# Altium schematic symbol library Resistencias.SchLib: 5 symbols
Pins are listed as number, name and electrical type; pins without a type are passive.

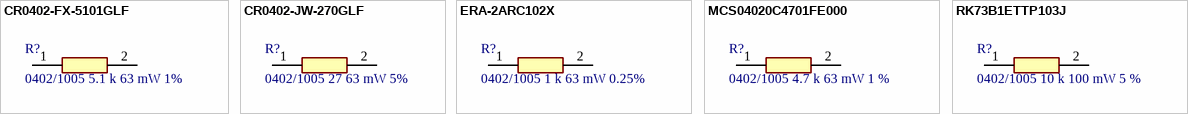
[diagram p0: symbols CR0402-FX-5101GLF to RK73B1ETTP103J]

## CR0402-FX-5101GLF
designator R?, comment 0402/1005 5.1 k 63 mW 1%
0402/1005 K 5.1 k 63 mW 1%; Manufacturer_Name: Bourns; Manufacturer_Part_Number: CR0402-FX-5101GLF; Description: Res Thick Film 0402 5.1K Ohm 1% 0.063W(1/16W) ±100ppm/C Pad SMD T/R; Voltage Rating (DC): 50V
footprint RESC1005X40N
pins: 1, 2

## CR0402-JW-270GLF
designator R?, comment 0402/1005 27 63 mW 5%
Manufacturer_Name: Bourns; Manufacturer_Part_Number: CR0402-JW-270GLF; Description: Res Thick Film 0402 27 Ohm 5% 1/16W ±200ppm/°C Molded SMD SMD Paper Tape on Plastic Reel
footprint RESC1005X40N
pins: 1, 2

## ERA-2ARC102X
designator R?, comment 0402/1005 1 k 63 mW 0.25%
0402/1005 k 1 63 mW 0.25%; Manufacturer_Name: Panasonic; Manufacturer_Part_Number: ERA-2ARC102X; Description: 0402 Thin Film Chip Resistor / 0402 SMD Resistor 0.25% 10PPM 1 Kohm; Value: 1kR; Max Power Dissipation: 63mW; Temperature Coefficient: 10ppm/°C
footprint ERA2AED122X
pins: 1, 2

## MCS04020C4701FE000
designator R?, comment 0402/1005 4.7 k 63 mW 1 %
0402/1005 k 4.7 63 mW 1 %; Manufacturer_Name: Vishay; Manufacturer_Part_Number: MCS04020C4701FE000; Manufacturer: Vishay Beyschlag; Description: Res Thin Film 0402 4.7K Ohm 1% 1/16W ±50ppm/°C Molded SMD SMD Paper T/R; Value: 4.7kR; Power Rating: 100mW; Tolerance: 1%; Voltage Rating: 50V; Temperature Coefficient: 50ppm/°C
footprint RESC1005X37N
pins: 1, 2

## RK73B1ETTP103J
designator R?, comment 0402/1005 10 k 100 mW 5 %
0402/1005 k 10 100 mW 5 %; Manufacturer_Name: KOA Speer; Manufacturer_Part_Number: RK73B1ETTP103J
footprint RESC1005X40N
pins: 1, 2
